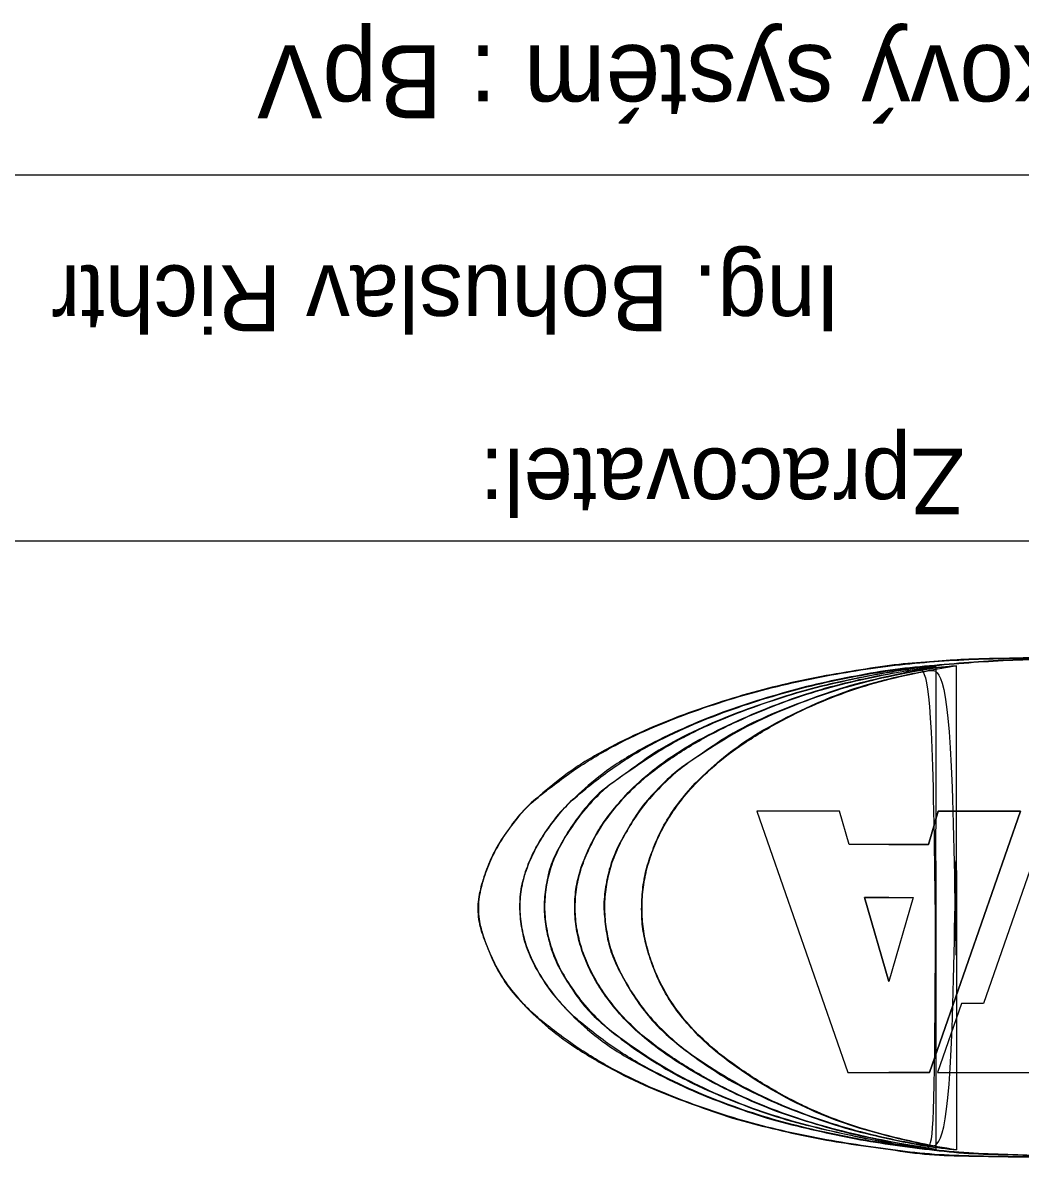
# Model space of a CAD drawing. Extents: x -728472.2 to -728419.7, y -1073099.3 to -1073025.
# Drawn here: x -728464.08 to -728457.28, y -1073054.87 to -1073046.99 of the extents above; entities that cross this region are included whole.
import ezdxf

# ---------------------------------------------------------------- set-up
doc = ezdxf.new("R2010")
doc.units = 0
doc.layers.add('_popis', color=7, linetype='Continuous')
doc.layers.add('Rozpiska_pole_6', color=7, linetype='Continuous')

msp = doc.modelspace()

# ---------------------------------------------------------------- linework, layer by layer
at = {"layer": '_popis'}
for p, q in [((-728458.3432, -1073052.9607), (-728458.1772, -1073052.9607)), ((-728458.1772, -1073053.5346), (-728458.3432, -1073052.9607))]:
    msp.add_line(p, q, dxfattribs=at)
for points in [[(-728458.1772, -1073052.5991), (-728458.4477, -1073052.5991), (-728458.5137, -1073052.3709), (-728459.0768, -1073052.3714), (-728458.4556, -1073054.1561), (-728458.1772, -1073054.1561)], [(-728458.1772, -1073052.5991), (-728458.4477, -1073052.5991), (-728458.5137, -1073052.3709), (-728459.0768, -1073052.3714), (-728458.4556, -1073054.1561), (-728458.1772, -1073054.1561)], [(-728458.1772, -1073052.5991), (-728457.9066, -1073052.5991), (-728457.8406, -1073052.3709), (-728457.2776, -1073052.3714), (-728457.8987, -1073054.1561), (-728458.1772, -1073054.1561)], [(-728458.1772, -1073054.1561), (-728457.8987, -1073054.1561), (-728457.2776, -1073052.3714), (-728457.8406, -1073052.3709), (-728457.9066, -1073052.5991), (-728458.1772, -1073052.5991)], [(-728456.7476, -1073054.1561), (-728456.5834, -1073053.6842), (-728456.7772, -1073053.6842), (-728456.5302, -1073052.9747), (-728456.7404, -1073052.3709), (-728457.0726, -1073052.3709), (-728457.5297, -1073053.6842), (-728457.6809, -1073053.6842), (-728457.8451, -1073054.1561), (-728456.7476, -1073054.1561)], [(-728456.7476, -1073054.1561), (-728456.5834, -1073053.6842), (-728456.7772, -1073053.6842), (-728456.5302, -1073052.9747), (-728456.7404, -1073052.3709), (-728457.0726, -1073052.3709), (-728457.5297, -1073053.6842), (-728457.6809, -1073053.6842), (-728457.8451, -1073054.1561), (-728456.7476, -1073054.1561)], [(-728458.1772, -1073052.9607), (-728458.3432, -1073052.9607), (-728458.1772, -1073053.5346)], [(-728458.1772, -1073052.9607), (-728458.0112, -1073052.9607), (-728458.1772, -1073053.5346)], [(-728458.1772, -1073052.9607), (-728458.0112, -1073052.9607), (-728458.1772, -1073053.5346)]]:
    msp.add_lwpolyline(points, dxfattribs=at)
for points in [[(-728457.7091, -1073051.3386), (-728457.7726, -1073051.3422), (-728457.925, -1073051.3531), (-728458.1678, -1073051.3735), (-728458.4349, -1073051.4173), (-728458.7039, -1073051.4628), (-728458.9726, -1073051.5237), (-728459.2412, -1073051.5978), (-728459.5099, -1073051.6866), (-728459.779, -1073051.7895), (-728460.0492, -1073051.9158), (-728460.3251, -1073052.0723), (-728460.5215, -1073052.2333), (-728460.6799, -1073052.366), (-728460.7644, -1073052.4858), (-728460.8578, -1073052.6154), (-728460.9179, -1073052.7534), (-728460.9631, -1073052.8875), (-728460.989, -1073053.0235), (-728460.9707, -1073053.1621), (-728460.9194, -1073053.2951), (-728460.8626, -1073053.4322), (-728460.7785, -1073053.5688), (-728460.681, -1073053.6813), (-728460.5301, -1073053.8296), (-728460.3243, -1073053.9851), (-728460.0511, -1073054.1448), (-728459.7818, -1073054.2742), (-728459.5101, -1073054.3742), (-728459.2438, -1073054.4708), (-728458.9726, -1073054.5378), (-728458.7045, -1073054.6), (-728458.434, -1073054.6453), (-728458.1654, -1073054.6802), (-728457.8989, -1073054.7218), (-728457.6308, -1073054.7247), (-728457.363, -1073054.7305), (-728457.1843, -1073054.7318), (-728457.0948, -1073054.7325)], [(-728457.0948, -1073054.7325), (-728456.7918, -1073054.7282), (-728456.5586, -1073054.7252), (-728456.2906, -1073054.7141), (-728456.0227, -1073054.6861), (-728455.7547, -1073054.644), (-728455.4862, -1073054.5975), (-728455.2182, -1073054.54), (-728454.9503, -1073054.4699), (-728454.6816, -1073054.3822), (-728454.4137, -1073054.2757), (-728454.1472, -1073054.1523), (-728453.8786, -1073053.9935), (-728453.6107, -1073053.7917), (-728453.5065, -1073053.6944), (-728453.3971, -1073053.5598), (-728453.3157, -1073053.4266), (-728453.2554, -1073053.292), (-728453.2231, -1073053.1586), (-728453.2078, -1073053.0243), (-728453.2217, -1073052.8922), (-728453.2624, -1073052.7568), (-728453.3227, -1073052.6222), (-728453.4069, -1073052.489), (-728453.5149, -1073052.3544), (-728453.6106, -1073052.265), (-728453.8785, -1073052.0617), (-728454.1464, -1073051.9103), (-728454.4116, -1073051.787), (-728454.6823, -1073051.6846), (-728454.9512, -1073051.5973), (-728455.2178, -1073051.5244), (-728455.4843, -1073051.4655), (-728455.7536, -1073051.4164), (-728456.0224, -1073051.3784), (-728456.2917, -1073051.349), (-728456.5568, -1073051.3307), (-728456.8269, -1073051.3278), (-728457.0948, -1073051.3234), (-728457.3627, -1073051.3278), (-728457.6315, -1073051.3348), (-728457.8994, -1073051.3516), (-728458.166, -1073051.3768), (-728458.4347, -1073051.4175), (-728458.7027, -1073051.4652), (-728458.9706, -1073051.5254), (-728459.2396, -1073051.5998), (-728459.5075, -1073051.6881), (-728459.7754, -1073051.7918), (-728460.042, -1073051.9166), (-728460.312, -1073052.0746), (-728460.5813, -1073052.2835), (-728460.6613, -1073052.355), (-728460.7665, -1073052.4882), (-728460.8549, -1073052.6214), (-728460.917, -1073052.7567), (-728460.9605, -1073052.8899), (-728460.9818, -1073053.0243), (-728460.9661, -1073053.158), (-728460.9198, -1073053.2926), (-728460.8594, -1073053.4295), (-728460.7795, -1073053.5599), (-728460.6659, -1073053.6944), (-728460.5831, -1073053.7758), (-728460.3122, -1073053.9854), (-728460.0443, -1073054.1438), (-728459.7781, -1073054.2707), (-728459.5088, -1073054.3745), (-728459.2395, -1073054.467), (-728458.9729, -1073054.5371), (-728458.7028, -1073054.5974), (-728458.4334, -1073054.6437), (-728458.1641, -1073054.6816), (-728457.8983, -1073054.7154), (-728457.6309, -1073054.7252), (-728457.3633, -1073054.7299), (-728457.0948, -1073054.7325), (-728457.0948, -1073054.7325), (-728457.0948, -1073054.7325)], [(-728457.0948, -1073054.7252), (-728457.1843, -1073054.7215), (-728457.3632, -1073054.7142), (-728457.6318, -1073054.7117), (-728457.8994, -1073054.6823), (-728458.1675, -1073054.6482), (-728458.4362, -1073054.6035), (-728458.704, -1073054.5443), (-728458.9744, -1073054.4802), (-728459.2417, -1073054.389), (-728459.5122, -1073054.2858), (-728459.7795, -1073054.1537), (-728460.0582, -1073054.0039), (-728460.2639, -1073053.84), (-728460.4163, -1073053.6872), (-728460.5124, -1073053.566), (-728460.5949, -1073053.4304), (-728460.6561, -1073053.296), (-728460.6882, -1073053.1591), (-728460.6999, -1073053.0238), (-728460.6897, -1073052.8873), (-728460.6489, -1073052.7527), (-728460.5887, -1073052.6175), (-728460.5032, -1073052.4835), (-728460.4121, -1073052.3643), (-728460.2577, -1073052.2194), (-728460.0581, -1073052.0546), (-728459.7814, -1073051.8986), (-728459.511, -1073051.7735), (-728459.242, -1073051.669), (-728458.9724, -1073051.5847), (-728458.7045, -1073051.51), (-728458.4353, -1073051.4543), (-728458.1674, -1073051.4053), (-728457.8986, -1073051.379), (-728457.6309, -1073051.356), (-728457.3632, -1073051.3388), (-728457.0947, -1073051.3301), (-728456.8264, -1073051.3401), (-728456.5586, -1073051.3592), (-728456.2898, -1073051.3739), (-728456.0214, -1073051.4058), (-728455.7529, -1073051.4493), (-728455.4847, -1073051.5062), (-728455.2148, -1073051.5726), (-728454.9483, -1073051.6648), (-728454.6772, -1073051.7619), (-728454.4059, -1073051.8851), (-728454.1363, -1073052.0484), (-728453.9248, -1073052.2091), (-728453.7633, -1073052.3565), (-728453.6669, -1073052.4825), (-728453.5871, -1073052.6187), (-728453.5268, -1073052.7533), (-728453.4896, -1073052.8885), (-728453.4658, -1073053.0241), (-728453.4866, -1073053.1601), (-728453.5212, -1073053.2956), (-728453.578, -1073053.4308), (-728453.6574, -1073053.5657), (-728453.754, -1073053.6974), (-728453.9216, -1073053.8464), (-728454.1329, -1073054.0145), (-728454.4102, -1073054.1627), (-728454.6774, -1073054.2922), (-728454.947, -1073054.3972), (-728455.2159, -1073054.4831), (-728455.4849, -1073054.5519), (-728455.714, -1073054.5973), (-728455.8931, -1073054.6301), (-728456.0715, -1073054.6588), (-728456.2898, -1073054.6909), (-728456.5585, -1073054.7078), (-728456.8266, -1073054.7189), (-728457.0054, -1073054.7231), (-728457.0948, -1073054.7252)], [(-728457.0948, -1073054.7252), (-728456.8266, -1073054.7181), (-728456.5587, -1073054.7069), (-728456.2908, -1073054.6872), (-728456.0228, -1073054.6508), (-728455.9022, -1073054.6312), (-728455.7549, -1073054.6045), (-728455.4863, -1073054.5496), (-728455.2183, -1073054.4809), (-728454.9498, -1073054.3951), (-728454.6819, -1073054.2899), (-728454.4136, -1073054.1622), (-728454.1471, -1073054.0122), (-728453.8788, -1073053.8071), (-728453.7594, -1073053.6946), (-728453.657, -1073053.5601), (-728453.5798, -1073053.4269), (-728453.5237, -1073053.2919), (-728453.4886, -1073053.1587), (-728453.4732, -1073053.0241), (-728453.4914, -1073052.8903), (-728453.5293, -1073052.7571), (-728453.5882, -1073052.6225), (-728453.6669, -1073052.4885), (-728453.7721, -1073052.3539), (-728453.8787, -1073052.253), (-728454.1467, -1073052.0483), (-728454.4136, -1073051.8879), (-728454.6815, -1073051.7645), (-728454.9494, -1073051.665), (-728455.218, -1073051.5761), (-728455.4859, -1073051.5074), (-728455.7539, -1073051.4514), (-728456.0225, -1073051.4076), (-728456.2904, -1073051.3767), (-728456.5584, -1073051.3585), (-728456.8268, -1073051.3416), (-728457.0948, -1073051.3332), (-728457.3627, -1073051.3402), (-728457.6314, -1073051.357), (-728457.8979, -1073051.3795), (-728458.1659, -1073051.4089), (-728458.4346, -1073051.4553), (-728458.7025, -1073051.5127), (-728458.9705, -1073051.5856), (-728459.2393, -1073051.6715), (-728459.5073, -1073051.7752), (-728459.7752, -1073051.9), (-728460.0437, -1073052.0565), (-728460.3117, -1073052.271), (-728460.3975, -1073052.3543), (-728460.5041, -1073052.4889), (-728460.5869, -1073052.6221), (-728460.6472, -1073052.7566), (-728460.685, -1073052.8898), (-728460.6963, -1073053.023), (-728460.685, -1073053.1581), (-728460.6528, -1073053.2913), (-728460.5939, -1073053.4259), (-728460.5124, -1073053.56), (-728460.4058, -1073053.6946), (-728460.3118, -1073053.7899), (-728460.0439, -1073054.0016), (-728459.7754, -1073054.1539), (-728459.5075, -1073054.2828), (-728459.2395, -1073054.388), (-728458.9711, -1073054.4765), (-728458.7031, -1073054.5438), (-728458.4352, -1073054.6013), (-728458.1666, -1073054.6466), (-728457.8986, -1073054.6816), (-728457.6314, -1073054.7072), (-728457.3635, -1073054.7156), (-728457.0948, -1073054.7252), (-728457.0948, -1073054.7252), (-728457.0948, -1073054.7252)], [(-728457.8541, -1073051.3831), (-728457.9054, -1073051.3873), (-728458.0106, -1073051.396), (-728458.2051, -1073051.4257), (-728458.4374, -1073051.4736), (-728458.7085, -1073051.5313), (-728458.9755, -1073051.6169), (-728459.245, -1073051.7097), (-728459.5148, -1073051.8264), (-728459.7886, -1073051.9731), (-728459.9788, -1073052.1233), (-728460.1483, -1073052.235), (-728460.2486, -1073052.3479), (-728460.3509, -1073052.4843), (-728460.4302, -1073052.6188), (-728460.4921, -1073052.7516), (-728460.5194, -1073052.8892), (-728460.5343, -1073053.0241), (-728460.5199, -1073053.1597), (-728460.4888, -1073053.2953), (-728460.4366, -1073053.4331), (-728460.3533, -1073053.5638), (-728460.2576, -1073053.7058), (-728460.1478, -1073053.8112), (-728459.9876, -1073053.9417), (-728459.786, -1073054.0831), (-728459.5144, -1073054.2361), (-728459.2428, -1073054.3499), (-728458.9755, -1073054.4518), (-728458.7052, -1073054.5243), (-728458.4347, -1073054.5852), (-728458.1673, -1073054.6384), (-728457.9736, -1073054.6729), (-728457.8692, -1073054.6792), (-728457.8552, -1073054.68)], [(-728457.8541, -1073051.3831), (-728458.0079, -1073051.3975), (-728458.1682, -1073051.4211), (-728458.4363, -1073051.4737), (-728458.7058, -1073051.5354), (-728458.9745, -1073051.6176), (-728459.2413, -1073051.7122), (-728459.5081, -1073051.8278), (-728459.7771, -1073051.9768), (-728460.0465, -1073052.1673), (-728460.1188, -1073052.2185), (-728460.2502, -1073052.3538), (-728460.3518, -1073052.491), (-728460.4294, -1073052.6224), (-728460.4872, -1073052.755), (-728460.5177, -1073052.891), (-728460.5295, -1073053.025), (-728460.5177, -1073053.1564), (-728460.4861, -1073053.293), (-728460.4335, -1073053.4279), (-728460.3546, -1073053.5605), (-728460.2587, -1073053.6945), (-728460.122, -1073053.8311), (-728460.0484, -1073053.8915), (-728459.7771, -1073054.0825), (-728459.5063, -1073054.2336), (-728459.2391, -1073054.3497), (-728458.975, -1073054.4469), (-728458.7008, -1073054.5235), (-728458.4353, -1073054.5839), (-728458.1659, -1073054.6377), (-728457.8972, -1073054.6773), (-728457.8552, -1073054.68), (-728457.8541, -1073051.3831), (-728457.8552, -1073054.68)], [(-728457.8552, -1073054.68), (-728457.9517, -1073054.6656), (-728458.146, -1073054.6364), (-728458.4299, -1073054.5781), (-728458.7064, -1073054.5019), (-728458.9767, -1073054.4126), (-728459.2443, -1073054.2943), (-728459.5149, -1073054.1526), (-728459.7519, -1073053.9979), (-728459.938, -1073053.8423), (-728460.0618, -1073053.6997), (-728460.1591, -1073053.5665), (-728460.2312, -1073053.4311), (-728460.2831, -1073053.2955), (-728460.314, -1073053.1594), (-728460.3231, -1073053.0235), (-728460.3133, -1073052.8884), (-728460.2793, -1073052.7528), (-728460.2217, -1073052.6195), (-728460.1512, -1073052.4818), (-728460.0502, -1073052.3496), (-728459.9278, -1073052.2104), (-728459.7482, -1073052.0553), (-728459.5149, -1073051.9033), (-728459.243, -1073051.7666), (-728458.9736, -1073051.6521), (-728458.7061, -1073051.5565), (-728458.4369, -1073051.4846), (-728458.1938, -1073051.4352), (-728457.9994, -1073051.4028), (-728457.8949, -1073051.3886), (-728457.8541, -1073051.3831)], [(-728457.8552, -1073054.68), (-728458.1443, -1073054.634), (-728458.4348, -1073054.5736), (-728458.7042, -1073054.5001), (-728458.9733, -1073054.409), (-728459.2388, -1073054.2934), (-728459.5069, -1073054.1515), (-728459.7757, -1073053.9734), (-728459.9439, -1073053.8289), (-728460.0635, -1073053.6936), (-728460.1582, -1073053.5609), (-728460.2291, -1073053.4283), (-728460.2806, -1073053.2923), (-728460.3108, -1073053.157), (-728460.32, -1073053.0243), (-728460.3095, -1073052.8894), (-728460.2766, -1073052.7567), (-728460.2214, -1073052.6227), (-728460.1491, -1073052.4874), (-728460.0519, -1073052.3548), (-728459.9321, -1073052.221), (-728459.773, -1073052.0818), (-728459.5075, -1073051.9058), (-728459.2381, -1073051.7678), (-728458.9706, -1073051.6539), (-728458.7024, -1073051.5594), (-728458.4356, -1073051.4871), (-728458.1669, -1073051.4317), (-728457.9763, -1073051.4001), (-728457.8541, -1073051.3831), (-728457.8552, -1073054.68), (-728457.8541, -1073051.3831)], [(-728457.7144, -1073051.3789), (-728457.776, -1073051.3842), (-728457.9287, -1073051.3973), (-728458.1678, -1073051.4486), (-728458.4383, -1073051.5094), (-728458.7051, -1073051.6019), (-728458.9756, -1073051.7058), (-728459.2499, -1073051.8358), (-728459.452, -1073051.979), (-728459.6314, -1073052.0973), (-728459.7499, -1073052.2148), (-728459.8716, -1073052.3459), (-728459.9544, -1073052.4868), (-728460.0313, -1073052.6179), (-728460.0831, -1073052.7528), (-728460.1115, -1073052.8881), (-728460.1264, -1073053.0237), (-728460.1102, -1073053.1589), (-728460.0891, -1073053.2957), (-728460.0336, -1073053.4298), (-728459.962, -1073053.5634), (-728459.8749, -1073053.7009), (-728459.7615, -1073053.838), (-728459.6334, -1073053.952), (-728459.4589, -1073054.0837), (-728459.2479, -1073054.2219), (-728458.9762, -1073054.3551), (-728458.7067, -1073054.46), (-728458.4389, -1073054.5482), (-728458.1689, -1073054.6094), (-728457.9284, -1073054.6592), (-728457.7758, -1073054.6766), (-728457.7143, -1073054.6836)], [(-728457.7144, -1073051.3789), (-728457.8986, -1073051.3979), (-728458.168, -1073051.4491), (-728458.4335, -1073051.5134), (-728458.703, -1073051.6028), (-728458.9717, -1073051.7082), (-728459.2385, -1073051.8395), (-728459.5072, -1073052.015), (-728459.6084, -1073052.0859), (-728459.7543, -1073052.2212), (-728459.87, -1073052.3539), (-728459.9555, -1073052.4886), (-728460.0291, -1073052.6226), (-728460.0803, -1073052.7566), (-728460.1092, -1073052.888), (-728460.1212, -1073053.0238), (-728460.1094, -1073053.1591), (-728460.0844, -1073053.2918), (-728460.0331, -1073053.425), (-728459.9609, -1073053.5616), (-728459.8754, -1073053.6942), (-728459.7637, -1073053.8289), (-728459.6165, -1073053.9629), (-728459.506, -1073054.047), (-728459.2389, -1073054.2197), (-728458.9721, -1073054.3523), (-728458.7027, -1073054.4587), (-728458.4365, -1073054.5443), (-728458.1684, -1073054.6086), (-728457.8985, -1073054.6603), (-728457.7143, -1073054.6836), (-728457.7144, -1073051.3789), (-728457.7143, -1073054.6836)], [(-728457.7143, -1073054.6836), (-728457.7759, -1073054.6747), (-728457.9281, -1073054.6526), (-728458.1682, -1073054.5933), (-728458.4394, -1073054.5212), (-728458.7098, -1073054.4158), (-728458.9794, -1073054.277), (-728459.2156, -1073054.1226), (-728459.409, -1073053.9738), (-728459.5443, -1073053.8341), (-728459.6508, -1073053.7004), (-728459.7315, -1073053.5647), (-728459.7897, -1073053.429), (-728459.8331, -1073053.2942), (-728459.8612, -1073053.1595), (-728459.8652, -1073053.0241), (-728459.8573, -1073052.8892), (-728459.8312, -1073052.7536), (-728459.7834, -1073052.6202), (-728459.7244, -1073052.4836), (-728459.6396, -1073052.3502), (-728459.5331, -1073052.2144), (-728459.398, -1073052.0814), (-728459.214, -1073051.9282), (-728458.9796, -1073051.7818), (-728458.7088, -1073051.6481), (-728458.44, -1073051.5384), (-728458.1691, -1073051.4632), (-728457.9271, -1073051.413), (-728457.7759, -1073051.3888), (-728457.7144, -1073051.3789)], [(-728457.7143, -1073054.6836), (-728457.8986, -1073054.6544), (-728458.1663, -1073054.593), (-728458.4355, -1073054.5169), (-728458.7032, -1073054.4131), (-728458.9716, -1073054.2753), (-728459.2393, -1073054.1013), (-728459.4153, -1073053.9614), (-728459.5455, -1073053.8284), (-728459.6508, -1073053.6939), (-728459.7298, -1073053.5608), (-728459.7883, -1073053.4263), (-728459.831, -1073053.2923), (-728459.8574, -1073053.1578), (-728459.8632, -1073053.0248), (-728459.8545, -1073052.8903), (-728459.8281, -1073052.7558), (-728459.7828, -1073052.6227), (-728459.7226, -1073052.4888), (-728459.6392, -1073052.3543), (-728459.5354, -1073052.2227), (-728459.4006, -1073052.0875), (-728459.2397, -1073051.9545), (-728458.972, -1073051.7834), (-728458.7038, -1073051.6497), (-728458.4361, -1073051.5429), (-728458.1655, -1073051.4654), (-728457.8988, -1073051.4096), (-728457.7144, -1073051.3789), (-728457.7143, -1073054.6836), (-728457.7144, -1073051.3789)], [(-728457.0948, -1073054.7325), (-728456.9938, -1073054.7309), (-728456.8151, -1073054.7281), (-728456.547, -1073054.7261), (-728456.29, -1073054.7173), (-728456.0217, -1073054.6887), (-728455.7543, -1073054.6438), (-728455.4853, -1073054.5997), (-728455.2169, -1073054.5415), (-728454.9477, -1073054.4722), (-728454.6787, -1073054.3847), (-728454.4114, -1073054.2766), (-728454.1391, -1073054.1548), (-728453.869, -1073053.9939), (-728453.6575, -1073053.836), (-728453.4965, -1073053.6898), (-728453.3973, -1073053.5665), (-728453.315, -1073053.4304), (-728453.2512, -1073053.297), (-728453.2219, -1073053.1596), (-728453.2018, -1073053.0253), (-728453.2182, -1073052.8883), (-728453.2607, -1073052.754), (-728453.3206, -1073052.6172), (-728453.4081, -1073052.4838), (-728453.5021, -1073052.3613), (-728453.661, -1073052.2185), (-728453.8658, -1073052.0597), (-728454.1406, -1073051.91), (-728454.409, -1073051.7834), (-728454.6797, -1073051.6836), (-728454.9485, -1073051.5958), (-728455.2161, -1073051.5222), (-728455.4843, -1073051.4641), (-728455.7525, -1073051.4146), (-728456.0221, -1073051.3771), (-728456.2898, -1073051.3478), (-728456.5581, -1073051.3266), (-728456.8262, -1073051.33), (-728457.0948, -1073051.3205), (-728457.363, -1073051.3286), (-728457.5679, -1073051.3314), (-728457.6832, -1073051.3371), (-728457.7091, -1073051.3386)]]:
    msp.add_open_spline(points, degree=3, dxfattribs=at)
at = {"layer": 'Rozpiska_pole_6'}
msp.add_line((-728424.685, -1073050.528), (-728467.185, -1073050.528), dxfattribs=at)
msp.add_lwpolyline([(-728424.685, -1073060.528), (-728467.185, -1073060.528), (-728467.185, -1073048.028), (-728424.685, -1073048.028)], close=True, dxfattribs=at)

# ---------------------------------------------------------------- texts
for s, height, p in [('Výškový systém : BpV', 0.5, (-728455.8741, -1073047.1432)), ('Ing. Bohuslav Richtr', 0.45, (-728458.509, -1073048.6463)), ('Zpracovatel:', 0.45, (-728457.6591, -1073049.8963))]:
    msp.add_text(s, height=height, rotation=180, dxfattribs=at).set_placement(p)

doc.saveas('drawing.dxf')
